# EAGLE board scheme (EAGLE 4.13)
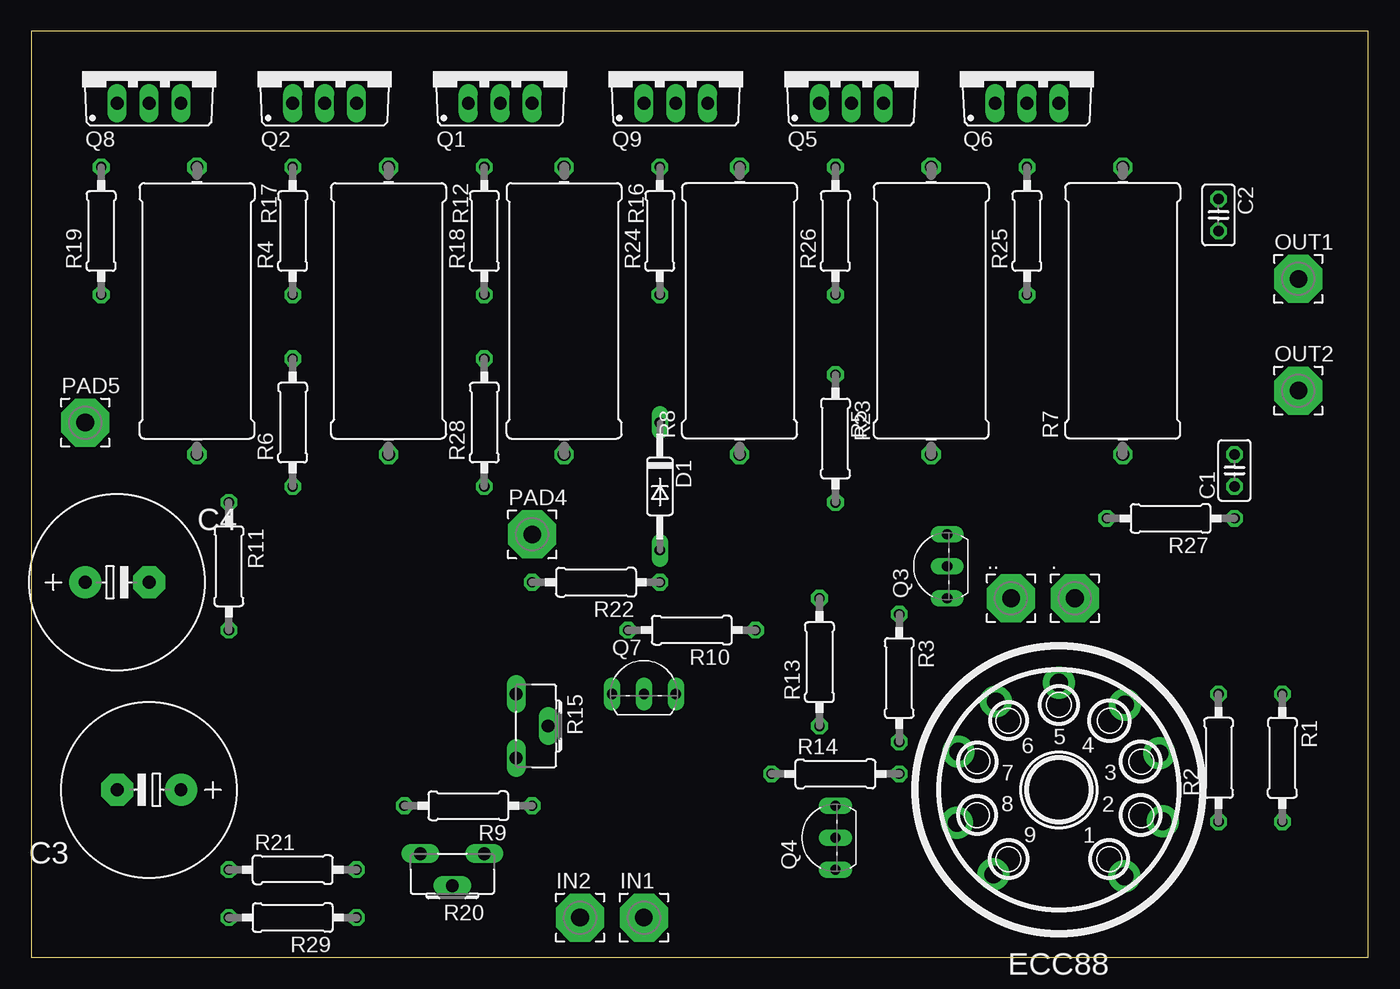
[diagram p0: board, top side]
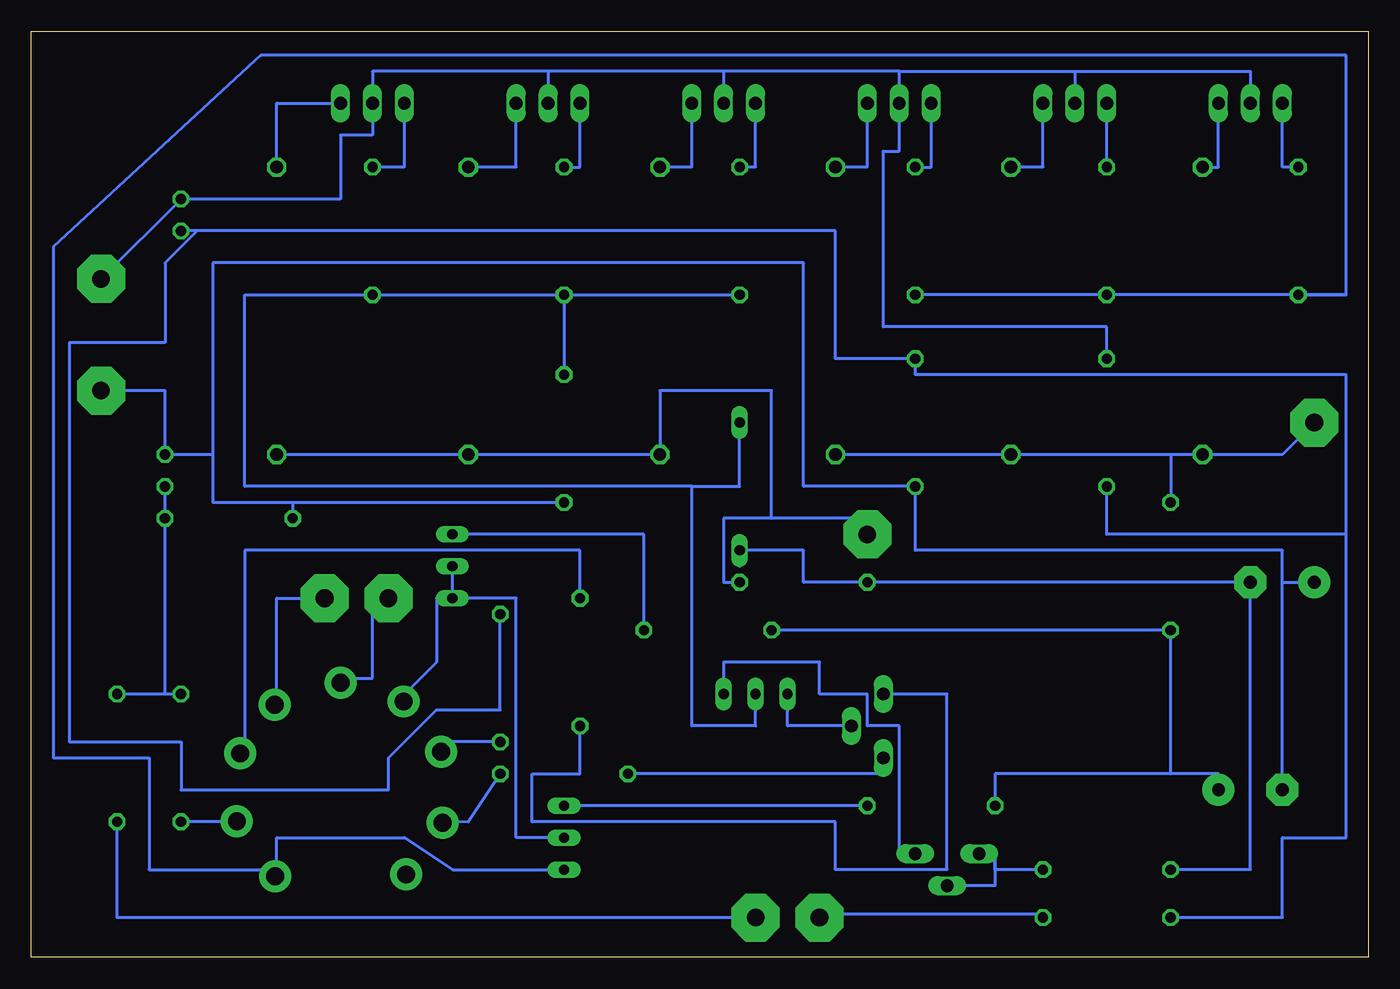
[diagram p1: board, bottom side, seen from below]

Size 106.35 x 73.65 mm. Coordinates in mm from the lower left corner, seen from the top.
Outline: 0,0 106.35,0 106.35,73.65 0,73.65 0,0
Copper layers (1*16): Top 0.035mm / dielectric 1.5mm / Bottom 0.035mm
Design rules "default": minimum track width 10mil, minimum drill 24mil, track to track 8mil, track to pad 8mil, pad to pad 8mil, via to via 8mil, smd to smd 8mil, copper to edge 40mil, drill to drill 8mil, minimum pad ring 10mil, minimum via ring 8mil, stop-mask expansion 4mil, vias tented up to drill 0mil, thermal gap 10mil

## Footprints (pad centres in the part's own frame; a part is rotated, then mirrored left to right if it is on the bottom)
3,81/1,4 = drill 1.397 pad 3.81 octagon: 1 0,0
C025-025X050 = drill 0.813 octagon: 1 -1.27,0; 2 1.27,0
E5-13 = drill 1.016 pad 2.54 round: + -2.54,0 | drill 1.016 pad 2.54 octagon: - 2.54,0
DO35-10 = drill 0.813 long: A 5.08,0; C -5.08,0
NOVAL = drill 1.422 pad 2.54 round: 1 5.207,-6.858; 2 8.254,-2.484; 3 8.004,2.893; 4 5.258,6.77; 5 0,8.524; 6 -5.004,7.024; 7 -8.004,3.02; 8 -8.127,-2.611; 9 -5.207,-6.731
TO220BV = drill 1.016 long: D 0,-2.54; G -2.54,-2.54; S 2.54,-2.54
TO92-EBC = drill 0.813 long: B 0,-1.27; C -2.54,-1.27; E 2.54,-1.27
0207/10 = drill 0.813 octagon: 1 -5.08,0; 2 5.08,0
0922/22 = drill 1.016 octagon: 1 -11.43,0; 2 11.43,0
CA6H = drill 1.016 long: A -2.54,0; E 2.54,0; S 0,2.54

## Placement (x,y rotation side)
.  HEAT+  [3,81/1,4]  83.02,28.57 0 top
..  HEAT-  [3,81/1,4]  77.94,28.57 0 top
C1  100pF  [C025-025X050]  95.72,38.73 90 top
C2  [C025-025X050]  94.45,59.05 270 top
C3  220uF  [E5-13]  9.36,13.33 180 top
C4  220uF  [E5-13]  6.82,29.84 0 top
D1  5V1  [DO35-10]  50,37.46 270 top
ECC88  [NOVAL]  81.75,13.33 0 top
IN1  IN  [3,81/1,4]  48.73,3.17 0 top
IN2  GND  [3,81/1,4]  43.65,3.17 0 top
OUT1  OUT  [3,81/1,4]  100.8,53.97 0 top
OUT2  GND  [3,81/1,4]  100.8,45.08 0 top
PAD4  -35  [3,81/1,4]  39.84,33.65 0 top
PAD5  +35  [3,81/1,4]  4.28,42.54 0 top
Q1  IRF9540  [TO220BV]  37.3,70.48 0 top
Q2  IRF9540  [TO220BV]  23.33,70.48 0 top
Q3  .  [TO92-EBC]  71.59,31.11 90 top
Q4  BC559  [TO92-EBC]  62.7,9.52 90 top
Q5  IRF540  [TO220BV]  65.24,70.48 0 top
Q6  IRF540  [TO220BV]  79.21,70.48 0 top
Q7  BC549C  [TO92-EBC]  48.73,22.22 0 top
Q8  IRF9540  [TO220BV]  9.36,70.48 0 top
Q9  IRF540  [TO220BV]  51.27,70.48 0 top
R1  10K  [0207/10]  99.53,15.87 270 top
R2  10K  [0207/10]  94.45,15.87 90 top
R3  100  [0207/10]  69.05,22.22 270 top
R4  100K  [0207/10]  20.79,57.78 90 top
R5  [0922/22]  71.59,51.43 90 top
R6  100K  [0207/10]  20.79,42.54 90 top
R7  [0922/22]  86.83,51.43 90 top
R8  [0922/22]  56.35,51.43 90 top
R9  510  [0207/10]  34.76,12.06 180 top
R10  510  [0207/10]  52.54,26.03 180 top
R11  100  [0207/10]  15.71,31.11 270 top
R12  [0922/22]  28.41,51.43 270 top
R13  100  [0207/10]  62.7,23.49 90 top
R14  100  [0207/10]  63.97,14.6 0 top
R15  [CA6H]  38.57,18.41 270 top
R16  [0922/22]  42.38,51.43 270 top
R17  [0922/22]  13.17,51.43 270 top
R18  100K  [0207/10]  36.03,57.78 90 top
R19  100K  [0207/10]  5.55,57.78 90 top
R20  4.7K  [CA6H]  33.49,8.25 180 top
R21  510  [0207/10]  20.79,6.98 0 top
R22  100  [0207/10]  44.92,29.84 180 top
R23  10K  [0207/10]  63.97,41.27 270 top
R24  100K  [0207/10]  50,57.78 90 top
R25  100K  [0207/10]  79.21,57.78 90 top
R26  100K  [0207/10]  63.97,57.78 90 top
R27  10K  [0207/10]  90.64,34.92 180 top
R28  10K  [0207/10]  36.03,42.54 90 top
R29  10K  [0207/10]  20.79,3.17 180 top

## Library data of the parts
. .. IN1 IN2 OUT1 OUT2 PAD4 PAD5 = wirepad
C1-C4 R1-R14 R16-R19 R21-R29 = rcl
D1 = diode
ECC88 = tubes
Q1 Q2 Q5 Q6 Q8 Q9 = transistor-power
Q3 Q4 = transistor-pnp
Q7 = transistor-npn
R15 R20 = pot

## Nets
GND: C1.2 C3.- C4.+ OUT2.1 R23.2 R27.2 R28.1
N$1: IN1.1 R1.2
N$2: ECC88.2 R2.1
N$3: ECC88.7 R3.2
N$4: ECC88.6 Q3.B Q3.C Q4.B
N$5: ECC88.1 Q4.C R4.1 R18.1 R19.1
N$6: Q6.S R7.2
N$7: Q1.S R16.1
N$8: C2.2 R3.1 R6.1 R28.2 R29.2
N$9: C2.1 OUT1.1 Q1.D Q2.D Q5.D Q6.D Q8.D Q9.D R6.2
N$10: Q2.S R12.1
N$11: Q1.G R18.2
N$12: Q4.E R9.1
N$13: Q3.E R10.1
N$14: C3.+ R9.2 R10.2 R11.2
N$15: PAD5.1 R11.1 R12.2 R16.2 R17.2
N$16: Q2.G R4.2
N$17: ECC88.3 R13.2
N$18: ECC88.8 R14.2
N$19: R13.1 R15.A
N$20: R14.1 R15.E
N$21: Q7.C R15.S
N$22: Q5.G R26.2
N$23: Q5.S R5.2
N$24: ..1 ECC88.4
N$25: Q9.G R24.2
N$26: D1.C Q7.B R23.1 R24.1 R25.1 R26.1
N$27: Q7.E R20.A
N$28: R20.E R20.S R21.2
N$29: PAD4.1 R5.1 R7.1 R8.1 R22.1
N$30: Q8.G R19.2
N$31: C4.- D1.A R21.1 R22.2
N$32: Q8.S R17.1
N$33: Q6.G R25.2
N$34: Q9.S R8.2
N$35: C1.1 R1.1 R2.2 R27.1
N$36: IN2.1 R29.1
N$37: ...1 ECC88.5

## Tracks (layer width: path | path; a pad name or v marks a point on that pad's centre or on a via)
GND
  Bottom 0.254: OUT2.1 95.72,45.08 C1.2 91.91,40 | 91.91,40 91.91,36.19 85.56,36.19 | 91.91,40 91.91,55.24 44.92,55.24 44.92,37.46 R28.1 36.03,32.38 6.82,32.38 6.82,29.84 | 6.82,29.84 C4.+ | C3.- 6.82,29.84 | 85.56,36.19 R23.2 | 85.56,36.19 R27.2
N$1
  Bottom 0.254: IN1.1 99.53,3.17 R1.2
N$2
  Bottom 0.254: R2.1 90.64,10.79 ECC88.2
N$3
  Bottom 0.254: R3.2 72.86,17.14 ECC88.7
N$4
  Bottom 0.254: Q3.C Q3.B | Q4.B 67.78,9.52 67.78,28.57 Q3.C | ECC88.6 76.67,20.95 74.13,23.49 74.13,28.57 Q3.C
N$5
  Bottom 0.254: R18.1 R4.1 1.74,52.7 | R19.1 1.74,52.7 | 1.74,52.7 1.74,71.75 88.1,71.75 104.61,56.51 104.61,15.87 96.99,15.87 96.99,6.98 88.1,6.98 ECC88.1 86.83,6.98 86.83,9.52 76.67,9.52 72.86,6.98 Q4.C
N$6
  Bottom 0.254: R7.2 86.83,67.94 Q6.S
N$7
  Bottom 0.254: R16.1 39.84,62.86 Q1.S
N$8
  Bottom 0.254: 93.18,57.78 42.38,57.78 42.38,47.62 R28.2 36.03,46.35 1.74,46.35 1.74,33.65 | 93.18,57.78 C2.2 | R3.1 69.05,19.68 74.13,19.68 77.94,15.87 77.94,13.33 94.45,13.33 94.45,17.14 103.34,17.14 103.34,48.89 95.72,48.89 95.72,55.24 93.18,57.78 | R29.2 6.82,3.17 6.82,9.52 1.74,9.52 1.74,33.65 | 1.74,33.65 20.79,33.65 R6.1
N$9
  Bottom 0.254: OUT1.1 C2.1 81.75,60.32 81.75,65.4 79.21,65.4 Q6.D 79.21,70.48 65.24,70.48 | 23.33,70.48 9.36,70.48 Q8.D | 23.33,70.48 Q2.D | 37.3,70.48 23.33,70.48 | 37.3,70.48 Q1.D 37.3,64.13 38.57,64.13 38.57,50.16 20.79,50.16 R6.2 | 37.3,70.48 51.27,70.48 | 51.27,70.48 Q9.D | 51.27,70.48 65.24,70.48 | 65.24,70.48 Q5.D
N$10
  Bottom 0.254: R12.1 25.87,62.86 Q2.S
N$11
  Bottom 0.254: R18.2 34.76,62.86 Q1.G
N$12
  Bottom 0.254: R9.1 Q4.E
N$13
  Bottom 0.254: Q3.E 57.62,33.65 R10.1
N$14
  Bottom 0.254: 15.71,14.6 29.68,14.6 R9.2 | 15.71,14.6 R11.2 R10.2 | C3.+ 11.9,14.6 15.71,14.6
N$15
  Bottom 0.254: R16.2 R12.2 15.71,40 | 15.71,40 R11.1 | 15.71,40 R17.2 6.82,40 PAD5.1
N$16
  Bottom 0.254: R4.2 Q2.G
N$17
  Bottom 0.254: ECC88.3 89.37,17.14 89.37,32.38 62.7,32.38 R13.2
N$18
  Bottom 0.254: R14.2 71.59,10.79 ECC88.8
N$19
  Bottom 0.254: R13.1 62.7,14.6 66.51,14.6 66.51,10.79 42.38,10.79 42.38,6.98 33.49,6.98 33.49,20.95 R15.A
N$20
  Bottom 0.254: R15.E 38.57,14.6 R14.1
N$21
  Bottom 0.254: Q7.C 46.19,18.41 R15.S
N$22
  Bottom 0.254: R26.2 62.7,62.86 Q5.G
N$23
  Bottom 0.254: R5.2 67.78,62.86 Q5.S
N$24
  Bottom 0.254: ECC88.4 86.83,20.95 86.83,28.57 ..1
N$25
  Bottom 0.254: R24.2 48.73,62.86 Q9.G
N$26
  Bottom 0.254: R26.1 R25.1 89.37,52.7 89.37,37.46 53.81,37.46 | R26.1 R24.1 | R26.1 R23.1 | 53.81,37.46 50,37.46 D1.C | 53.81,37.46 53.81,18.41 48.73,18.41 Q7.B
N$27
  Bottom 0.254: R20.A 37.3,8.25 37.3,18.41 39.84,18.41 39.84,20.95 43.65,20.95 43.65,23.49 51.27,23.49 Q7.E
N$28
  Bottom 0.254: R21.2 29.68,6.98 29.68,8.25 | 29.68,8.25 29.68,5.71 R20.S | 29.68,8.25 R20.E
N$29
  Bottom 0.254: R7.1 R5.1 R8.1 56.35,45.08 47.46,45.08 47.46,34.92 | R22.1 51.27,29.84 51.27,34.92 47.46,34.92 | 47.46,34.92 41.11,34.92 PAD4.1
N$30
  Bottom 0.254: R19.2 6.82,62.86 Q8.G
N$31
  Bottom 0.254: 50,31.11 D1.A 44.92,32.38 44.92,29.84 R22.2 C4.- 9.36,6.98 R21.1
N$32
  Bottom 0.254: R17.1 11.9,62.86 Q8.S
N$33
  Bottom 0.254: R25.2 76.67,62.86 Q6.G
N$34
  Bottom 0.254: R8.2 53.81,62.86 Q9.S
N$35
  Bottom 0.254: C1.1 R27.1 95.72,20.95 R2.2 R1.1
N$36
  Bottom 0.254: R29.1 26.12,3.42 42.89,3.42 IN2.1
N$37
  Bottom 0.254: ECC88.5 81.75,22.22 79.21,22.22 79.21,27.3 76.67,27.3 ...1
